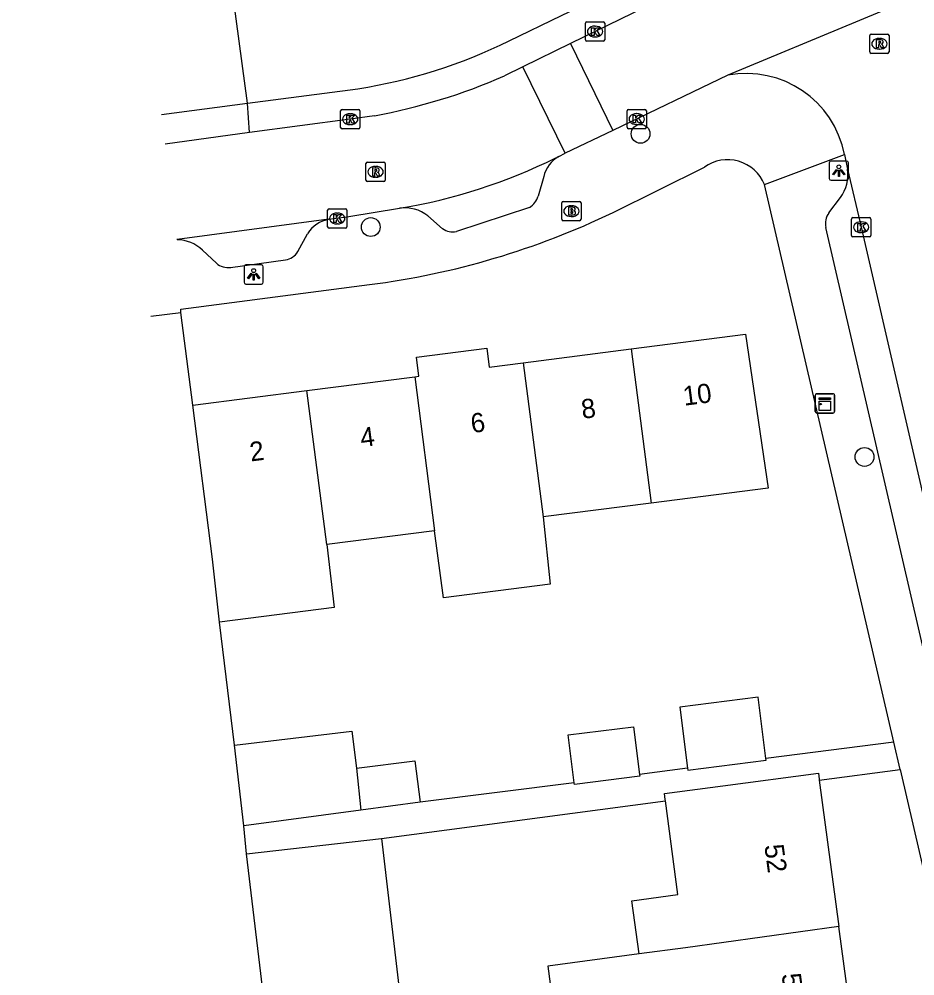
# Model space of a CAD drawing. Extents: x 163427 to 164190, y 380331 to 381641.
# Drawn here: x 163524.16 to 163570.7, y 381284.84 to 381334.51 of the extents above; entities that cross this region are included whole.
import ezdxf

# ---------------------------------------------------------------- set-up
doc = ezdxf.new("R2010")
doc.units = 0
for name, color, linetype in [('IMGEO_Boom', 7, 'Continuous'), ('IMGEO_Brandkraan', 7, 'Continuous'), ('IMGEO_Kast', 7, 'Continuous'), ('IMGEO_Kolk', 7, 'Continuous'), ('IMGEO_Lichtpunt', 7, 'Continuous'), ('IMGEO_Pand', 7, 'Continuous'), ('IMGEO_Pand_nummerreeks', 7, 'Continuous'), ('IMGEO_Rijbaan_lokaal_open', 7, 'Continuous'), ('IMGEO_Rioolput', 7, 'Continuous'), ('IMGEO_Voetpad_open', 7, 'Continuous')]:
    doc.layers.add(name, color=color, linetype=linetype)

msp = doc.modelspace()

# ---------------------------------------------------------------- linework, layer by layer
at = {"layer": 'IMGEO_Boom'}
for centre in [(163556.446, 381328.551), (163542.43, 381323.711), (163568.082, 381311.776)]:
    msp.add_circle(centre, 0.489, dxfattribs=at)
at = {"layer": 'IMGEO_Brandkraan'}
for p, q in [((163552.355, 381324.112), (163552.355, 381324.964)), ((163552.43, 381325.038), (163553.282, 381325.038)), ((163552.843, 381324.818), (163552.868, 381324.818)), ((163553.356, 381324.964), (163553.356, 381324.112)), ((163552.866, 381324.258), (163552.841, 381324.258)), ((163553.282, 381324.038), (163552.43, 381324.038))]:
    msp.add_line(p, q, dxfattribs=at)
for points in [[(163552.355, 381324.112), (163552.355, 381324.964)], [(163552.43, 381325.038), (163553.282, 381325.038)], [(163552.703, 381324.738), (163552.703, 381324.338), (163552.916, 381324.338)], [(163552.934, 381324.738), (163552.703, 381324.738)], [(163553.356, 381324.964), (163553.356, 381324.112)], [(163552.882, 381324.657), (163552.828, 381324.657), (163552.828, 381324.581)], [(163552.828, 381324.581), (163552.881, 381324.581)], [(163552.89, 381324.505), (163552.828, 381324.505), (163552.828, 381324.424)], [(163552.828, 381324.424), (163552.89, 381324.424)], [(163553.282, 381324.038), (163552.43, 381324.038)]]:
    msp.add_lwpolyline(points, dxfattribs=at)
for centre, radius, start, end in [((163552.432, 381324.962), 0.0765, 91.552, 178.448), ((163552.432, 381324.962), 0.0765, 91.552, 178.448), ((163552.938, 381324.593), 0.145, 59.4692, 91.5367), ((163552.963, 381324.64), 0.0922, 285.5137, 58.1501), ((163553.28, 381324.962), 0.0765, 1.552, 88.448), ((163553.28, 381324.962), 0.0765, 1.552, 88.448), ((163552.883, 381324.619), 0.0379, 267.8285, 90.9355), ((163552.891, 381324.464), 0.0404, 269.8759, 90.5077), ((163552.922, 381324.589), 0.251, 268.6676, 293.5347), ((163552.968, 381324.448), 0.105, 301.3115, 78.989), ((163552.432, 381324.114), 0.0765, 181.552, 268.448), ((163552.432, 381324.114), 0.0765, 181.552, 268.448), ((163553.28, 381324.114), 0.0765, 271.552, 358.448), ((163553.28, 381324.114), 0.0765, 271.552, 358.448)]:
    msp.add_arc(centre, radius, start, end, dxfattribs=at)
for centre, major_axis, ratio, start_param, end_param in [((163552.842, 381324.538), (-0.387, 0.002), 0.722429, 4.712389, 7.853982), ((163552.867, 381324.538), (-0.39, 0.002), 0.717154, 1.570796, 4.712389)]:
    msp.add_ellipse(centre, major_axis=major_axis, ratio=ratio, start_param=start_param, end_param=end_param, dxfattribs=at)
at = {"layer": 'IMGEO_Kast'}
for p, q in [((163565.522, 381314.132), (163565.522, 381314.973)), ((163565.522, 381314.973), (163565.522, 381314.132)), ((163565.597, 381315.057), (163566.438, 381315.057)), ((163566.438, 381315.057), (163565.597, 381315.057)), ((163566.522, 381314.982), (163566.522, 381314.141)), ((163566.522, 381314.141), (163566.522, 381314.982)), ((163566.447, 381314.057), (163565.606, 381314.057)), ((163565.606, 381314.057), (163566.447, 381314.057))]:
    msp.add_line(p, q, dxfattribs=at)
for points in [[(163565.717, 381314.847), (163566.317, 381314.847), (163566.317, 381314.762), (163565.717, 381314.762), (163565.717, 381314.847)], [(163565.717, 381314.672), (163566.317, 381314.672), (163566.317, 381314.183), (163565.717, 381314.183), (163565.717, 381314.672)]]:
    msp.add_lwpolyline(points, dxfattribs=at)
msp.add_circle((163565.801, 381314.521), 0.0377, dxfattribs=at)
for centre, start, end in [((163565.6, 381314.979), 92.4484, 184.2845), ((163565.6, 381314.979), 92.4484, 184.2845), ((163566.444, 381314.979), 2.4484, 94.2845), ((163566.444, 381314.979), 2.4484, 94.2845), ((163565.6, 381314.135), 182.4484, 274.2845), ((163565.6, 381314.135), 182.4484, 274.2845), ((163566.444, 381314.135), 272.4484, 4.2845), ((163566.444, 381314.135), 272.4484, 4.2845)]:
    msp.add_arc(centre, 0.0779, start, end, dxfattribs=at)
at = {"layer": 'IMGEO_Kolk'}
for p, q in [((163553.584, 381333.436), (163553.584, 381334.288)), ((163553.659, 381334.362), (163554.511, 381334.362)), ((163554.072, 381334.142), (163554.097, 381334.142)), ((163554.585, 381334.288), (163554.585, 381333.436)), ((163554.511, 381333.362), (163553.659, 381333.362)), ((163554.095, 381333.582), (163554.07, 381333.582)), ((163540.862, 381328.887), (163540.862, 381329.739)), ((163540.937, 381329.813), (163541.789, 381329.813)), ((163541.863, 381329.739), (163541.863, 381328.887)), ((163555.747, 381328.892), (163555.747, 381329.744)), ((163555.822, 381329.818), (163556.674, 381329.818)), ((163556.748, 381329.744), (163556.748, 381328.892)), ((163541.35, 381329.593), (163541.375, 381329.593)), ((163556.235, 381329.598), (163556.26, 381329.598)), ((163541.789, 381328.813), (163540.937, 381328.813)), ((163541.373, 381329.033), (163541.348, 381329.033)), ((163556.674, 381328.818), (163555.822, 381328.818)), ((163556.258, 381329.038), (163556.233, 381329.038)), ((163540.188, 381323.729), (163540.188, 381324.581)), ((163540.263, 381324.655), (163541.115, 381324.655)), ((163540.676, 381324.435), (163540.701, 381324.435)), ((163541.189, 381324.581), (163541.189, 381323.729)), ((163567.481, 381324.2), (163568.333, 381324.2)), ((163540.699, 381323.875), (163540.674, 381323.875)), ((163567.406, 381323.274), (163567.406, 381324.126)), ((163567.894, 381323.98), (163567.919, 381323.98)), ((163568.407, 381324.126), (163568.407, 381323.274)), ((163541.115, 381323.655), (163540.263, 381323.655)), ((163568.333, 381323.2), (163567.481, 381323.2)), ((163567.917, 381323.42), (163567.892, 381323.42))]:
    msp.add_line(p, q, dxfattribs=at)
for points in [[(163553.584, 381333.436), (163553.584, 381334.288)], [(163553.659, 381334.362), (163554.511, 381334.362)], [(163554.585, 381334.288), (163554.585, 381333.436)], [(163553.905, 381334.062), (163554.028, 381334.062), (163554.028, 381333.911), (163554.158, 381334.062), (163554.322, 381334.062), (163554.176, 381333.911), (163554.329, 381333.662), (163554.177, 381333.662), (163554.092, 381333.826), (163554.028, 381333.759), (163554.028, 381333.662), (163553.905, 381333.662), (163553.905, 381334.062)], [(163554.511, 381333.362), (163553.659, 381333.362)], [(163540.862, 381328.887), (163540.862, 381329.739)], [(163540.937, 381329.813), (163541.789, 381329.813)], [(163541.863, 381329.739), (163541.863, 381328.887)], [(163555.747, 381328.892), (163555.747, 381329.744)], [(163555.822, 381329.818), (163556.674, 381329.818)], [(163556.748, 381329.744), (163556.748, 381328.892)], [(163541.183, 381329.513), (163541.306, 381329.513), (163541.306, 381329.362), (163541.436, 381329.513), (163541.6, 381329.513), (163541.454, 381329.362), (163541.607, 381329.113), (163541.455, 381329.113), (163541.37, 381329.277), (163541.306, 381329.21), (163541.306, 381329.113), (163541.183, 381329.113), (163541.183, 381329.513)], [(163556.068, 381329.518), (163556.191, 381329.518), (163556.191, 381329.367), (163556.321, 381329.518), (163556.485, 381329.518), (163556.339, 381329.367), (163556.492, 381329.118), (163556.34, 381329.118), (163556.255, 381329.282), (163556.191, 381329.215), (163556.191, 381329.118), (163556.068, 381329.118), (163556.068, 381329.518)], [(163541.789, 381328.813), (163540.937, 381328.813)], [(163556.674, 381328.818), (163555.822, 381328.818)], [(163540.188, 381323.729), (163540.188, 381324.581)], [(163540.263, 381324.655), (163541.115, 381324.655)], [(163540.509, 381324.355), (163540.632, 381324.355), (163540.632, 381324.204), (163540.762, 381324.355), (163540.926, 381324.355), (163540.78, 381324.204), (163540.933, 381323.955), (163540.781, 381323.955), (163540.696, 381324.119), (163540.632, 381324.052), (163540.632, 381323.955), (163540.509, 381323.955), (163540.509, 381324.355)], [(163541.189, 381324.581), (163541.189, 381323.729)], [(163567.481, 381324.2), (163568.333, 381324.2)], [(163567.406, 381323.274), (163567.406, 381324.126)], [(163567.727, 381323.9), (163567.85, 381323.9), (163567.85, 381323.749), (163567.98, 381323.9), (163568.144, 381323.9), (163567.998, 381323.749), (163568.151, 381323.5), (163567.999, 381323.5), (163567.914, 381323.664), (163567.85, 381323.597), (163567.85, 381323.5), (163567.727, 381323.5), (163567.727, 381323.9)], [(163568.407, 381324.126), (163568.407, 381323.274)], [(163541.115, 381323.655), (163540.263, 381323.655)], [(163568.333, 381323.2), (163567.481, 381323.2)]]:
    msp.add_lwpolyline(points, dxfattribs=at)
for centre, start, end in [((163553.661, 381334.286), 91.552, 178.448), ((163553.661, 381334.286), 91.552, 178.448), ((163554.509, 381334.286), 1.552, 88.448), ((163554.509, 381334.286), 1.552, 88.448), ((163553.661, 381333.438), 181.552, 268.448), ((163553.661, 381333.438), 181.552, 268.448), ((163554.509, 381333.438), 271.552, 358.448), ((163554.509, 381333.438), 271.552, 358.448), ((163540.939, 381329.737), 91.552, 178.448), ((163540.939, 381329.737), 91.552, 178.448), ((163541.787, 381329.737), 1.552, 88.448), ((163541.787, 381329.737), 1.552, 88.448), ((163555.824, 381329.742), 91.552, 178.448), ((163555.824, 381329.742), 91.552, 178.448), ((163556.672, 381329.742), 1.552, 88.448), ((163556.672, 381329.742), 1.552, 88.448), ((163540.939, 381328.889), 181.552, 268.448), ((163540.939, 381328.889), 181.552, 268.448), ((163541.787, 381328.889), 271.552, 358.448), ((163541.787, 381328.889), 271.552, 358.448), ((163555.824, 381328.894), 181.552, 268.448), ((163555.824, 381328.894), 181.552, 268.448), ((163556.672, 381328.894), 271.552, 358.448), ((163556.672, 381328.894), 271.552, 358.448), ((163540.265, 381324.579), 91.552, 178.448), ((163540.265, 381324.579), 91.552, 178.448), ((163541.113, 381324.579), 1.552, 88.448), ((163541.113, 381324.579), 1.552, 88.448), ((163567.483, 381324.124), 91.552, 178.448), ((163567.483, 381324.124), 91.552, 178.448), ((163568.331, 381324.124), 1.552, 88.448), ((163568.331, 381324.124), 1.552, 88.448), ((163540.265, 381323.731), 181.552, 268.448), ((163540.265, 381323.731), 181.552, 268.448), ((163541.113, 381323.731), 271.552, 358.448), ((163541.113, 381323.731), 271.552, 358.448), ((163567.483, 381323.276), 181.552, 268.448), ((163567.483, 381323.276), 181.552, 268.448), ((163568.331, 381323.276), 271.552, 358.448), ((163568.331, 381323.276), 271.552, 358.448)]:
    msp.add_arc(centre, 0.0765, start, end, dxfattribs=at)
for centre, major_axis, ratio, start_param, end_param in [((163554.071, 381333.862), (-0.387, 0.002), 0.722429, 4.712389, 7.853982), ((163554.096, 381333.862), (-0.39, 0.002), 0.717154, 1.570796, 4.712389), ((163541.349, 381329.313), (-0.387, 0.002), 0.722429, 4.712389, 7.853982), ((163541.374, 381329.313), (-0.39, 0.002), 0.717154, 1.570796, 4.712389), ((163556.234, 381329.318), (-0.387, 0.002), 0.722429, 4.712389, 7.853982), ((163556.259, 381329.318), (-0.39, 0.002), 0.717154, 1.570796, 4.712389), ((163540.675, 381324.155), (-0.387, 0.002), 0.722429, 4.712389, 7.853982), ((163540.7, 381324.155), (-0.39, 0.002), 0.717154, 1.570796, 4.712389), ((163567.893, 381323.7), (-0.387, 0.002), 0.722429, 4.712389, 7.853982), ((163567.918, 381323.7), (-0.39, 0.002), 0.717154, 1.570796, 4.712389)]:
    msp.add_ellipse(centre, major_axis=major_axis, ratio=ratio, start_param=start_param, end_param=end_param, dxfattribs=at)
at = {"layer": 'IMGEO_Lichtpunt'}
for p, q in [((163566.25, 381327.042), (163566.25, 381326.235)), ((163566.25, 381327.042), (163566.25, 381326.235)), ((163567.152, 381327.137), (163566.344, 381327.137)), ((163567.152, 381327.137), (163566.344, 381327.137)), ((163567.246, 381326.235), (163567.246, 381327.042)), ((163567.246, 381326.235), (163567.246, 381327.042)), ((163566.344, 381326.141), (163567.152, 381326.141)), ((163566.344, 381326.141), (163567.152, 381326.141)), ((163536.751, 381321.748), (163535.943, 381321.748)), ((163536.751, 381321.748), (163535.943, 381321.748)), ((163535.849, 381321.653), (163535.849, 381320.846)), ((163535.849, 381321.653), (163535.849, 381320.846)), ((163536.845, 381320.846), (163536.845, 381321.653)), ((163536.845, 381320.846), (163536.845, 381321.653)), ((163535.943, 381320.752), (163536.751, 381320.752)), ((163535.943, 381320.752), (163536.751, 381320.752))]:
    msp.add_line(p, q, dxfattribs=at)
for points in [[(163566.624, 381326.706), (163566.663, 381326.678), (163566.475, 381326.416), (163566.437, 381326.443), (163566.624, 381326.706)], [(163566.836, 381326.678), (163566.874, 381326.705), (163567.061, 381326.443), (163567.022, 381326.415), (163566.836, 381326.678)], [(163566.726, 381326.658), (163566.773, 381326.658), (163566.773, 381326.336), (163566.726, 381326.336), (163566.726, 381326.658)], [(163536.223, 381321.317), (163536.262, 381321.289), (163536.074, 381321.027), (163536.036, 381321.054), (163536.223, 381321.317)], [(163536.325, 381321.269), (163536.372, 381321.269), (163536.372, 381320.947), (163536.325, 381320.947), (163536.325, 381321.269)], [(163536.435, 381321.289), (163536.473, 381321.316), (163536.66, 381321.054), (163536.621, 381321.026), (163536.435, 381321.289)]]:
    msp.add_lwpolyline(points, dxfattribs=at)
for centre in [(163566.749, 381326.84), (163536.348, 381321.451)]:
    msp.add_circle(centre, 0.0994, dxfattribs=at)
for centre, start, end in [((163566.344, 381327.042), 90, 180), ((163566.344, 381327.042), 90, 180), ((163567.152, 381327.042), 0, 90), ((163567.152, 381327.042), 0, 90), ((163566.344, 381326.235), 180, 270), ((163566.344, 381326.235), 180, 270), ((163567.152, 381326.235), 270, 0), ((163567.152, 381326.235), 270, 360), ((163535.943, 381321.653), 90, 180), ((163535.943, 381321.653), 90, 180), ((163536.751, 381321.653), 0, 90), ((163536.751, 381321.653), 0, 90), ((163535.943, 381320.846), 180, 270), ((163535.943, 381320.846), 180, 270), ((163536.751, 381320.846), 270, 0), ((163536.751, 381320.846), 270, 360)]:
    msp.add_arc(centre, 0.0946, start, end, dxfattribs=at)
at = {"layer": 'IMGEO_Pand'}
for points in [[(163555.964, 381317.385), (163561.89, 381318.147), (163563.075, 381310.154), (163556.993, 381309.377)], [(163544.715, 381315.94), (163544.935, 381315.968), (163544.813, 381316.949), (163548.464, 381317.415), (163548.585, 381316.437), (163550.355, 381316.665)], [(163550.355, 381316.665), (163555.964, 381317.385)], [(163555.964, 381317.385), (163556.993, 381309.377)], [(163550.355, 381316.665), (163551.383, 381308.66)], [(163539.116, 381315.22), (163544.715, 381315.94)], [(163544.715, 381315.94), (163545.743, 381307.939)], [(163533.192, 381314.459), (163539.116, 381315.22)], [(163540.143, 381307.223), (163539.116, 381315.22)], [(163534.577, 381303.2), (163534.214, 381306.465), (163533.192, 381314.459)], [(163556.993, 381309.377), (163551.383, 381308.66)], [(163551.383, 381308.66), (163551.745, 381305.173), (163546.207, 381304.463), (163545.743, 381307.939)], [(163545.743, 381307.939), (163540.143, 381307.223)], [(163540.143, 381307.223), (163540.528, 381303.963), (163534.577, 381303.2)], [(163562.962, 381296.124), (163562.56, 381299.313), (163558.493, 381298.787), (163558.885, 381295.611)], [(163535.349, 381296.807), (163541.442, 381297.537), (163541.683, 381295.616)], [(163553.004, 381294.865), (163552.692, 381297.346), (163556.082, 381297.773), (163556.394, 381295.295)], [(163535.832, 381292.618), (163535.349, 381296.807)], [(163541.683, 381295.616), (163544.72, 381296.004), (163544.995, 381293.849)], [(163558.885, 381295.611), (163558.896, 381295.521), (163562.973, 381296.035), (163562.962, 381296.124)], [(163541.683, 381295.616), (163541.913, 381293.435)], [(163556.394, 381295.295), (163556.405, 381295.206), (163553.015, 381294.779), (163553.004, 381294.865)], [(163557.735, 381293.931), (163557.728, 381293.986), (163557.686, 381294.302), (163560.724, 381294.703), (163565.681, 381295.357), (163565.723, 381295.041), (163565.729, 381294.993)], [(163565.729, 381294.993), (163566.747, 381287.4)], [(163556.368, 381285.975), (163555.996, 381288.733), (163558.388, 381289.058), (163557.735, 381293.931)], [(163541.913, 381293.435), (163535.832, 381292.618)], [(163544.995, 381293.849), (163541.913, 381293.435)], [(163535.974, 381291.167), (163542.985, 381291.97)], [(163542.985, 381291.97), (163543.883, 381284.302)], [(163536.906, 381283.368), (163535.974, 381291.167)], [(163566.747, 381287.4), (163558.772, 381286.297), (163556.368, 381285.975)], [(163567.506, 381281.74), (163566.747, 381287.4)], [(163556.368, 381285.975), (163551.624, 381285.34), (163552.38, 381279.696), (163557.128, 381280.333)]]:
    msp.add_lwpolyline(points, dxfattribs=at)
at = {"layer": 'IMGEO_Rijbaan_lokaal_open'}
for points in [[(163536.034, 381330.138), (163524.164, 381418.345)], [(163574.663, 381337.293), (163560.974, 381331.591)], [(163559.248, 381336.383), (163552.802, 381333.234)], [(163552.802, 381333.234), (163550.323, 381332.021)], [(163552.802, 381333.234), (163555.008, 381328.727)], [(163550.323, 381332.021), (163549.372, 381331.556)], [(163552.536, 381327.541), (163550.323, 381332.021)], [(163560.974, 381331.591), (163555.008, 381328.727)], [(163531.559, 381329.55), (163531.559, 381329.55), (163536.034, 381330.138)], [(163542.618, 381329.49), (163541.358, 381329.311), (163536.124, 381328.613)], [(163555.008, 381328.727), (163552.536, 381327.541)], [(163536.124, 381328.613), (163531.749, 381328.021)], [(163552.051, 381327.302), (163552.177, 381327.364), (163552.199, 381327.375)], [(163552.199, 381327.375), (163552.536, 381327.541)], [(163567.036, 381327.472), (163567.201, 381326.721)], [(163567.201, 381326.721), (163567.904, 381323.7), (163572.087, 381305.625), (163572.362, 381304.745)], [(163540.261, 381324.117), (163541.288, 381324.254), (163543.922, 381324.683)], [(163540.261, 381324.117), (163532.366, 381323.067), (163532.365, 381323.067)], [(163531.005, 381319.076), (163531.005, 381319.076), (163532.572, 381319.278)], [(163533.192, 381314.459), (163532.572, 381319.278)], [(163535.349, 381296.807), (163534.577, 381303.2)], [(163535.974, 381291.167), (163535.832, 381292.618)]]:
    msp.add_lwpolyline(points, dxfattribs=at)
for centre, radius, start, end in [((163561.943, 381326.497), 5.186, 10.8425, 100.767), ((163536.987, 381359.972), 30.998, 280.4669, 293.5501), ((163539.031, 381353.791), 29.516, 279.5393, 296.1764)]:
    msp.add_arc(centre, radius, start, end, dxfattribs=at)
at = {"layer": 'IMGEO_Rioolput'}
for p, q in [((163568.355, 381332.8), (163568.355, 381333.652)), ((163568.43, 381333.726), (163569.282, 381333.726)), ((163569.356, 381333.652), (163569.356, 381332.8)), ((163568.843, 381333.506), (163568.868, 381333.506)), ((163569.282, 381332.726), (163568.43, 381332.726)), ((163568.866, 381332.946), (163568.841, 381332.946)), ((163542.178, 381326.152), (163542.178, 381327.004)), ((163542.253, 381327.078), (163543.105, 381327.078)), ((163542.666, 381326.858), (163542.691, 381326.858)), ((163543.179, 381327.004), (163543.179, 381326.152)), ((163542.689, 381326.298), (163542.664, 381326.298)), ((163543.105, 381326.078), (163542.253, 381326.078))]:
    msp.add_line(p, q, dxfattribs=at)
for points in [[(163568.355, 381332.8), (163568.355, 381333.652)], [(163568.43, 381333.726), (163569.282, 381333.726)], [(163569.356, 381333.652), (163569.356, 381332.8)], [(163568.944, 381333.424), (163568.692, 381333.426), (163568.692, 381333.026)], [(163568.692, 381333.026), (163568.816, 381333.026), (163568.816, 381333.188), (163568.827, 381333.188)], [(163568.87, 381333.345), (163568.816, 381333.345), (163568.816, 381333.264)], [(163568.816, 381333.264), (163568.868, 381333.264)], [(163568.874, 381333.159), (163568.945, 381333.026), (163569.085, 381333.026), (163569.02, 381333.152)], [(163569.282, 381332.726), (163568.43, 381332.726)], [(163542.178, 381326.152), (163542.178, 381327.004)], [(163542.253, 381327.078), (163543.105, 381327.078)], [(163542.767, 381326.776), (163542.515, 381326.778), (163542.515, 381326.378)], [(163542.693, 381326.697), (163542.639, 381326.697), (163542.639, 381326.616)], [(163543.179, 381327.004), (163543.179, 381326.152)], [(163542.515, 381326.378), (163542.639, 381326.378), (163542.639, 381326.54), (163542.65, 381326.54)], [(163542.639, 381326.616), (163542.691, 381326.616)], [(163542.697, 381326.511), (163542.768, 381326.378), (163542.908, 381326.378), (163542.843, 381326.504)], [(163543.105, 381326.078), (163542.253, 381326.078)]]:
    msp.add_lwpolyline(points, dxfattribs=at)
for centre, radius, start, end in [((163568.432, 381333.65), 0.0765, 91.552, 178.448), ((163568.432, 381333.65), 0.0765, 91.552, 178.448), ((163569.28, 381333.65), 0.0765, 1.552, 88.448), ((163569.28, 381333.65), 0.0765, 1.552, 88.448), ((163568.826, 381333.135), 0.0533, 26.0293, 88.6989), ((163568.852, 381333.453), 0.19, 274.7715, 282.9687), ((163568.876, 381333.249), 0.0964, 77.0061, 93.1865), ((163568.89, 381333.306), 0.0378, 276.6634, 79.6772), ((163568.943, 381333.314), 0.109, 350.3612, 89.416), ((163568.941, 381333.314), 0.112, 277.5842, 350.9817), ((163568.925, 381333.099), 0.108, 29.5134, 73.7905), ((163568.432, 381332.802), 0.0765, 181.552, 268.448), ((163568.432, 381332.802), 0.0765, 181.552, 268.448), ((163569.28, 381332.802), 0.0765, 271.552, 358.448), ((163569.28, 381332.802), 0.0765, 271.552, 358.448), ((163542.255, 381327.002), 0.0765, 91.552, 178.448), ((163542.255, 381327.002), 0.0765, 91.552, 178.448), ((163542.699, 381326.601), 0.0964, 77.0061, 93.1865), ((163542.713, 381326.658), 0.0378, 276.6634, 79.6772), ((163542.766, 381326.666), 0.109, 350.3612, 89.416), ((163543.103, 381327.002), 0.0765, 1.552, 88.448), ((163543.103, 381327.002), 0.0765, 1.552, 88.448), ((163542.649, 381326.487), 0.0533, 26.0293, 88.6989), ((163542.675, 381326.805), 0.19, 274.7715, 282.9687), ((163542.764, 381326.666), 0.112, 277.5842, 350.9817), ((163542.748, 381326.451), 0.108, 29.5134, 73.7905), ((163542.255, 381326.154), 0.0765, 181.552, 268.448), ((163542.255, 381326.154), 0.0765, 181.552, 268.448), ((163543.103, 381326.154), 0.0765, 271.552, 358.448), ((163543.103, 381326.154), 0.0765, 271.552, 358.448)]:
    msp.add_arc(centre, radius, start, end, dxfattribs=at)
for centre, major_axis, ratio, start_param, end_param in [((163568.842, 381333.226), (-0.387, 0.002), 0.722429, 4.712389, 7.853982), ((163568.867, 381333.226), (-0.39, 0.002), 0.717154, 1.570796, 4.712389), ((163542.665, 381326.578), (-0.387, 0.002), 0.722429, 4.712389, 7.853982), ((163542.69, 381326.578), (-0.39, 0.002), 0.717154, 1.570796, 4.712389)]:
    msp.add_ellipse(centre, major_axis=major_axis, ratio=ratio, start_param=start_param, end_param=end_param, dxfattribs=at)
at = {"layer": 'IMGEO_Voetpad_open'}
for points in [[(163549.628, 381333.382), (163552.342, 381334.7), (163556.158, 381336.539)], [(163536.034, 381330.138), (163541.759, 381330.889)], [(163536.124, 381328.613), (163536.034, 381330.138)], [(163562.879, 381325.922), (163567.036, 381327.472)], [(163555.018, 381324.466), (163559.766, 381326.822)], [(163551.417, 381326.332), (163551.12, 381325.322)], [(163569.602, 381296.96), (163562.879, 381325.922)], [(163566.23, 381324.441), (163566.829, 381325.237)], [(163550.675, 381324.732), (163546.88, 381323.481)], [(163546.161, 381323.627), (163545.397, 381324.286)], [(163538.641, 381322.438), (163539.138, 381323.364)], [(163574.878, 381285.631), (163566.07, 381323.69)], [(163533.687, 381322.518), (163534.409, 381321.837)], [(163535.153, 381321.611), (163538.001, 381322.002)], [(163532.572, 381319.278), (163532.561, 381319.454), (163542.371, 381320.72)], [(163569.602, 381296.96), (163562.962, 381296.124)], [(163569.929, 381295.551), (163569.602, 381296.96)], [(163558.885, 381295.611), (163556.394, 381295.295)], [(163565.729, 381294.993), (163569.929, 381295.551)], [(163569.929, 381295.551), (163573.656, 381279.496), (163569.808, 381264.93), (163571.382, 381253.255)], [(163553.004, 381294.865), (163544.995, 381293.849)], [(163542.985, 381291.97), (163557.735, 381293.931)]]:
    msp.add_lwpolyline(points, dxfattribs=at)
for centre, radius, start, end in [((163537.5, 381357.998), 27.441, 278.9286, 296.2291), ((163552.99, 381325.968), 1.614, 119.3243, 166.9535), ((163560.97, 381325.153), 2.058, 21.938, 125.8118), ((163565.188, 381326.437), 2.033, 323.8251, 8.0298), ((163550.167, 381325.578), 0.987, 300.9823, 344.9678), ((163544.213, 381322.826), 1.88, 50.9603, 98.9111), ((163537.042, 381361.933), 41.556, 277.3675, 295.6307), ((163566.958, 381323.893), 0.911, 143.0555, 192.8905), ((163540.566, 381322.448), 1.697, 100.3653, 147.3204), ((163546.693, 381324.404), 0.941, 235.5841, 281.4591), ((163532.34, 381321.083), 1.968, 46.8067, 89.2033), ((163537.853, 381322.907), 0.918, 279.3035, 329.2258), ((163535.032, 381322.55), 0.947, 228.8541, 277.3521)]:
    msp.add_arc(centre, radius, start, end, dxfattribs=at)

# ---------------------------------------------------------------- texts
at = {"layer": 'IMGEO_Pand_nummerreeks'}
for s, rotation, p in [('10', 7.323, (163558.712, 381314.432)), ('8', 7.323, (163553.43, 381313.752)), ('6', 7.323, (163547.687, 381313.015)), ('4', 7.323, (163541.947, 381312.277)), ('2', 7.323, (163536.205, 381311.538)), ('52', 277.6316, (163562.874, 381291.607)), ('54', 277.6316, (163563.771, 381284.914))]:
    msp.add_text(s, height=1, rotation=rotation, dxfattribs=at).set_placement(p)

doc.saveas('drawing.dxf')
